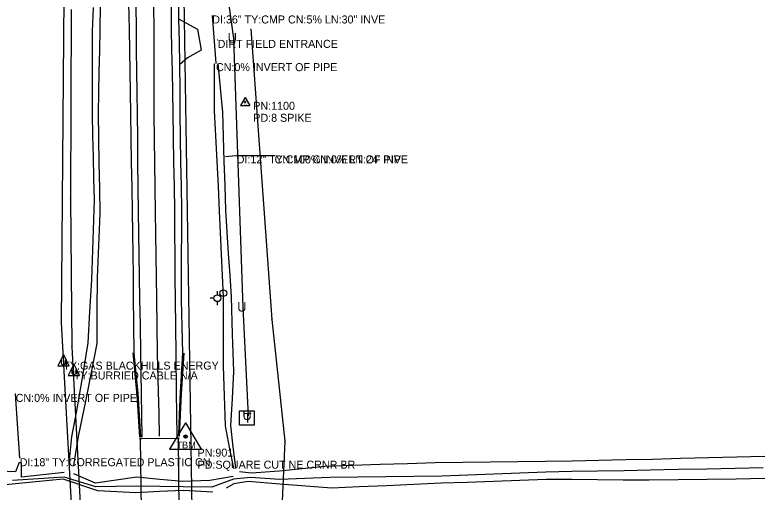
# Model space of a CAD drawing. Extents: x 1804576 to 1805329, y 515859 to 519427.
# Drawn here: x 1804860.5 to 1805328.7, y 517731.6 to 518029.7 of the extents above; entities that cross this region are included whole.
import ezdxf

# ---------------------------------------------------------------- set-up
doc = ezdxf.new("R2010")
doc.units = 0
for name, color, linetype in [('Default', 7, 'Continuous'), ('S_BASELINE', 7, 'Continuous'), ('S_BRIDGE', 7, 'Continuous'), ('S_DITCHLINE', 7, 'Continuous'), ('S_DRG_PT_SYM', 7, 'Continuous'), ('S_EDGE_PAVEMENT', 7, 'Continuous'), ('S_FIBER_OPTIC_CABLE', 7, 'Continuous'), ('S_GAS_UTILITIES', 7, 'Continuous'), ('S_GUARDRAIL', 7, 'Continuous'), ('S_MSC_PT_SYM', 7, 'Continuous'), ('S_PAVEMENT_CROWN', 7, 'Continuous'), ('S_PRIMARY_CTL', 7, 'Continuous'), ('S_PRIMARY_CTL_ANNOT', 7, 'Continuous'), ('S_RDW_PT_SYM', 7, 'Continuous'), ('S_SECONDARY_CTL', 7, 'Continuous'), ('S_SECONDARY_CTL_ANNOT', 7, 'Continuous'), ('S_SHOULDER', 7, 'Continuous'), ('S_SIDE_DRAIN', 7, 'Continuous'), ('S_SIDE_DRAIN_ANNOT', 7, 'Continuous'), ('S_STR_PT_SYM', 7, 'Continuous'), ('S_STREAM', 7, 'Continuous'), ('S_SURVEY_TEXT_ANNOT', 7, 'Continuous'), ('S_TELEPHONE_UTILITIES', 7, 'Continuous'), ('S_UNDERGROUND_CABLE', 7, 'Continuous'), ('S_UTILITY_POLE', 7, 'Continuous'), ('S_UTILITY_POLE_ANNOT', 7, 'Continuous'), ('S_UTL_PT_SYM', 7, 'Continuous'), ('S_WATER_UTILITIES', 7, 'Continuous')]:
    doc.layers.add(name, color=color, linetype=linetype)

msp = doc.modelspace()

# ---------------------------------------------------------------- linework, layer by layer
at = {"layer": 'S_BASELINE'}
msp.add_line((1804971.48, 517701.71), (1804956.7, 518650.01), dxfattribs=at)
at = {"layer": 'S_BRIDGE'}
for p, q in [((1804962.51, 517765.12), (1804938.7, 517764.9)), ((1804938.7, 517764.9), (1804939.34, 517710.14)), ((1804963.12, 517709.92), (1804962.51, 517765.12))]:
    msp.add_line(p, q, dxfattribs=at)
at = {"layer": 'S_DITCHLINE'}
for points in [[(1804913.71, 518035.48), (1804913.53, 518020.43), (1804913.24, 518007.38), (1804912.95, 517994.34), (1804912.66, 517981.29), (1804912.36, 517968.24), (1804912.67, 517952.61), (1804912.98, 517936.98), (1804913.28, 517921.36), (1804913.59, 517905.73), (1804912.67, 517885.64), (1804911.75, 517865.55), (1804911.69, 517844.94), (1804911.63, 517824.33), (1804908.12, 517806.31), (1804904.61, 517788.3), (1804899.95, 517766.31), (1804897.02, 517748.26)], [(1804909.37, 518034.43), (1804908.79, 518019.3), (1804908.77, 518006.38), (1804908.74, 517993.46), (1804908.72, 517980.54), (1804908.69, 517967.62), (1804909, 517954.28), (1804909.31, 517940.94), (1804909.62, 517927.61), (1804909.93, 517914.27), (1804909.51, 517901.75), (1804909.09, 517889.24), (1804908.67, 517876.72), (1804908.25, 517864.2), (1804907.14, 517844.47), (1804906.03, 517824.74), (1804902.39, 517803.02), (1804898.75, 517781.29), (1804895.9, 517766.12), (1804894.15, 517749.44)], [(1804985.12, 517999.01), (1804984.78, 517999.09), (1804984.83, 517984.42), (1804984.88, 517969.74), (1804985.68, 517954.08), (1804986.48, 517938.42), (1804987.28, 517922.76), (1804988.09, 517907.1), (1804988.69, 517893.68), (1804989.29, 517880.25), (1804989.9, 517866.83), (1804990.5, 517853.4), (1804990.47, 517831.79), (1804990.43, 517810.18), (1804991.06, 517791.61), (1804991.69, 517773.04), (1804994.27, 517759.64), (1804996.86, 517746.25)], [(1804987.06, 517999.41), (1804988.57, 517984.22), (1804990.08, 517969.02), (1804990.55, 517953.71), (1804991.01, 517938.39), (1804991.48, 517923.07), (1804991.94, 517907.75), (1804992.82, 517894.23), (1804993.7, 517880.7), (1804994.57, 517867.18), (1804995.45, 517853.65), (1804996.19, 517830.26), (1804996.93, 517806.87), (1804996.01, 517790.01), (1804995.1, 517773.14), (1804996.61, 517759.89), (1804998.12, 517746.64)], [(1804991.99, 517941.17), (1804998.45, 517941.88)]]:
    msp.add_lwpolyline(points, dxfattribs=at)
at = {"layer": 'S_DRG_PT_SYM'}
for points in [[(1804983.65, 518029.36), (1804983.65, 518029.41), (1804983.65, 518029.36), (1804983.6, 518029.36), (1804983.65, 518029.36), (1804983.65, 518029.31), (1804983.65, 518029.36), (1804983.7, 518029.36)], [(1804986, 517999.57), (1804986, 517999.62), (1804986, 517999.57), (1804985.95, 517999.57), (1804986, 517999.57), (1804986, 517999.52), (1804986, 517999.57), (1804986.05, 517999.57)], [(1804998.95, 517941.96), (1804998.95, 517942.01), (1804998.95, 517941.96), (1804998.9, 517941.96), (1804998.95, 517941.96), (1804998.95, 517941.91), (1804998.95, 517941.96), (1804999, 517941.96)], [(1805022.6, 517941.9), (1805022.6, 517941.95), (1805022.6, 517941.9), (1805022.55, 517941.9), (1805022.6, 517941.9), (1805022.6, 517941.85), (1805022.6, 517941.9), (1805022.65, 517941.9)], [(1804860.96, 517792.93), (1804860.96, 517792.98), (1804860.96, 517792.93), (1804860.91, 517792.93), (1804860.96, 517792.93), (1804860.96, 517792.88), (1804860.96, 517792.93), (1804861.01, 517792.93)], [(1804863.51, 517752.75), (1804863.51, 517752.8), (1804863.51, 517752.75), (1804863.46, 517752.75), (1804863.51, 517752.75), (1804863.51, 517752.7), (1804863.51, 517752.75), (1804863.56, 517752.75)]]:
    msp.add_lwpolyline(points, dxfattribs=at)
at = {"layer": 'S_EDGE_PAVEMENT'}
for points in [[(1804958.01, 518041.11), (1804958.03, 518020.98), (1804958.3, 518007.82), (1804958.57, 517994.65), (1804958.85, 517981.49), (1804959.12, 517968.32), (1804959.34, 517953.08), (1804959.57, 517937.84), (1804959.8, 517922.6), (1804960.03, 517907.36), (1804960.14, 517893.43), (1804960.26, 517879.5), (1804960.37, 517865.58), (1804960.48, 517851.65), (1804960.72, 517834.92), (1804960.96, 517818.19), (1804961.15, 517793.95), (1804961.35, 517780.35), (1804961.55, 517766.75)], [(1804935.89, 518035.71), (1804936.1, 518021), (1804936.27, 518007.71), (1804936.45, 517994.43), (1804936.63, 517981.15), (1804936.8, 517967.87), (1804936.96, 517952.61), (1804937.11, 517937.35), (1804937.27, 517922.09), (1804937.42, 517906.83), (1804937.65, 517893.23), (1804937.87, 517879.62), (1804938.1, 517866.02), (1804938.32, 517852.42), (1804938.58, 517835.57), (1804938.83, 517818.71), (1804939.04, 517805.94), (1804939.25, 517793.16), (1804939.43, 517779.49), (1804939.62, 517765.81)], [(1804962.68, 518027.24), (1804974.55, 518020.85), (1804976.66, 518007.75), (1804968.17, 518002.88), (1804963.33, 517998.5)]]:
    msp.add_lwpolyline(points, dxfattribs=at)
at = {"layer": 'S_FIBER_OPTIC_CABLE'}
for p, q in [((1804895.65, 518033.06), (1804895.12, 517915.08)), ((1804895.12, 517915.08), (1804895.93, 517822.38)), ((1804895.93, 517822.38), (1804902.15, 517708.69))]:
    msp.add_line(p, q, dxfattribs=at)
at = {"layer": 'S_GAS_UTILITIES'}
for p, q in [((1804891.14, 518041.91), (1804889.37, 517837.53)), ((1804889.37, 517837.53), (1804897.25, 517695.47))]:
    msp.add_line(p, q, dxfattribs=at)
at = {"layer": 'S_GUARDRAIL'}
for p, q in [((1804934.14, 517818.53), (1804936.62, 517792.02)), ((1804965.9, 517818.28), (1804964.18, 517792.93)), ((1804936.62, 517792.02), (1804938.31, 517766.07)), ((1804964.18, 517792.93), (1804963.03, 517766.47))]:
    msp.add_line(p, q, dxfattribs=at)
at = {"layer": 'S_MSC_PT_SYM'}
msp.add_lwpolyline([(1804987.06, 518014.13), (1804987.06, 518014.18), (1804987.06, 518014.13), (1804987.01, 518014.13), (1804987.06, 518014.13), (1804987.06, 518014.08), (1804987.06, 518014.13), (1804987.11, 518014.13)], dxfattribs=at)
at = {"layer": 'S_PAVEMENT_CROWN'}
msp.add_lwpolyline([(1804947.1, 518035.51), (1804947.26, 518020.62), (1804947.26, 518007.32), (1804947.27, 517994.03), (1804947.27, 517980.73), (1804947.28, 517967.43), (1804947.45, 517952.23), (1804947.61, 517937.03), (1804947.78, 517921.84), (1804947.95, 517906.64), (1804948.18, 517893.02), (1804948.41, 517879.41), (1804948.64, 517865.79), (1804948.87, 517852.18), (1804949.09, 517835.31), (1804949.31, 517818.44), (1804949.91, 517794.33), (1804950.25, 517780.37), (1804950.59, 517766.42)], dxfattribs=at)
at = {"layer": 'S_PRIMARY_CTL'}
for p, q in [((1804966.99, 517774.9), (1804956.96, 517758.39)), ((1804966.99, 517774.9), (1804976.81, 517758.39)), ((1804956.96, 517758.39), (1804976.81, 517758.39))]:
    msp.add_line(p, q, dxfattribs=at)
for radius in [1.04, 0.609, 0.344]:
    msp.add_circle((1804966.99, 517766.2), radius, dxfattribs=at)
at = {"layer": 'S_RDW_PT_SYM'}
for points in [[(1804934.14, 517818.53), (1804934.14, 517818.58), (1804934.14, 517818.53), (1804934.09, 517818.53), (1804934.14, 517818.53), (1804934.14, 517818.48), (1804934.14, 517818.53), (1804934.19, 517818.53)], [(1804965.9, 517818.28), (1804965.9, 517818.33), (1804965.9, 517818.28), (1804965.85, 517818.28), (1804965.9, 517818.28), (1804965.9, 517818.23), (1804965.9, 517818.28), (1804965.95, 517818.28)], [(1804936.62, 517792.02), (1804936.62, 517792.07), (1804936.62, 517792.02), (1804936.57, 517792.02), (1804936.62, 517792.02), (1804936.62, 517791.97), (1804936.62, 517792.02), (1804936.67, 517792.02)], [(1804964.18, 517792.93), (1804964.18, 517792.98), (1804964.18, 517792.93), (1804964.13, 517792.93), (1804964.18, 517792.93), (1804964.18, 517792.88), (1804964.18, 517792.93), (1804964.23, 517792.93)], [(1804938.31, 517766.07), (1804938.31, 517766.12), (1804938.31, 517766.07), (1804938.26, 517766.07), (1804938.31, 517766.07), (1804938.31, 517766.02), (1804938.31, 517766.07), (1804938.36, 517766.07)], [(1804963.03, 517766.47), (1804963.03, 517766.52), (1804963.03, 517766.47), (1804962.98, 517766.47), (1804963.03, 517766.47), (1804963.03, 517766.42), (1804963.03, 517766.47), (1804963.08, 517766.47)]]:
    msp.add_lwpolyline(points, dxfattribs=at)
at = {"layer": 'S_SECONDARY_CTL'}
for p, q in [((1805004.29, 517978.04), (1805001.28, 517973.09)), ((1805004.29, 517978.04), (1805007.24, 517973.09)), ((1805001.28, 517973.09), (1805007.24, 517973.09))]:
    msp.add_line(p, q, dxfattribs=at)
for radius in [0.311, 0.183, 0.103]:
    msp.add_circle((1805004.29, 517975.43), radius, dxfattribs=at)
at = {"layer": 'S_SHOULDER'}
for points in [[(1804931.49, 518037.31), (1804931.74, 518020.57), (1804931.95, 518007.44), (1804932.16, 517994.32), (1804932.37, 517981.19), (1804932.58, 517968.06), (1804932.86, 517952.73), (1804933.15, 517937.4), (1804933.43, 517922.07), (1804933.72, 517906.74), (1804933.88, 517893.48), (1804934.04, 517880.21), (1804934.21, 517866.95), (1804934.37, 517853.68), (1804934.51, 517836.07), (1804934.64, 517818.46), (1804935.89, 517805.92), (1804937.13, 517793.37), (1804937.98, 517779.58), (1804938.84, 517765.78)], [(1804962.51, 518040.03), (1804962.67, 518027.32), (1804963, 518012.92), (1804963.33, 517998.52), (1804963.34, 517983.44), (1804963.36, 517968.36), (1804963.64, 517953.17), (1804963.92, 517937.98), (1804964.2, 517922.8), (1804964.49, 517907.61), (1804964.42, 517893.61), (1804964.35, 517879.61), (1804964.29, 517865.62), (1804964.22, 517851.62), (1804964.62, 517835.06), (1804965.03, 517818.5), (1804963.56, 517793.85), (1804963.07, 517780.26), (1804962.58, 517766.68)]]:
    msp.add_lwpolyline(points, dxfattribs=at)
at = {"layer": 'S_SIDE_DRAIN'}
for p, q in [((1804983.65, 518029.36), (1804986, 517999.57)), ((1804998.95, 517941.96), (1805022.6, 517941.9)), ((1804863.51, 517752.75), (1804860.96, 517792.93))]:
    msp.add_line(p, q, dxfattribs=at)
at = {"layer": 'S_STR_PT_SYM'}
for points in [[(1804938.7, 517764.9), (1804938.7, 517765.4), (1804938.7, 517764.9), (1804938.2, 517764.9), (1804938.7, 517764.9), (1804938.7, 517764.4), (1804938.7, 517764.9), (1804939.2, 517764.9)], [(1804962.51, 517765.12), (1804962.51, 517765.62), (1804962.51, 517765.12), (1804962.01, 517765.12), (1804962.51, 517765.12), (1804962.51, 517764.62), (1804962.51, 517765.12), (1804963.01, 517765.12)]]:
    msp.add_lwpolyline(points, dxfattribs=at)
at = {"layer": 'S_STREAM'}
for points in [[(1804891.18, 517743.82), (1804877.94, 517742.32), (1804864.7, 517740.81), (1804864.65, 517749.6), (1804863.08, 517749.98), (1804860.8, 517744.12), (1804845.91, 517744.83), (1804831.02, 517745.55), (1804815.66, 517744.74), (1804800.29, 517743.92), (1804784.93, 517743.11), (1804769.56, 517742.3), (1804753.95, 517742.37), (1804738.34, 517742.44), (1804722.73, 517742.52), (1804707.12, 517742.59), (1804689.69, 517741.98), (1804672.25, 517741.37), (1804654.82, 517740.76), (1804637.38, 517740.15), (1804623.03, 517739.12), (1804608.68, 517738.09), (1804594.32, 517737.06), (1804579.97, 517736.03)], [(1805328.55, 517753.75), (1805311.05, 517753.32), (1805293.56, 517752.88), (1805276.06, 517752.45), (1805258.57, 517752.01), (1805241.8, 517751.67), (1805225.03, 517751.33), (1805208.26, 517750.99), (1805191.49, 517750.65), (1805174.33, 517750.45), (1805157.17, 517750.26), (1805140.01, 517750.07), (1805122.86, 517749.87), (1805105.65, 517749.3), (1805088.45, 517748.72), (1805071.25, 517748.15), (1805054.04, 517747.58), (1805039.73, 517746.06), (1805025.41, 517744.54), (1805008.18, 517743.49), (1805000.64, 517744.21)], [(1805327.64, 517746.68), (1805310, 517746.33), (1805292.35, 517745.97), (1805274.71, 517745.61), (1805257.07, 517745.26), (1805240.76, 517744.95), (1805224.45, 517744.65), (1805208.14, 517744.34), (1805191.83, 517744.04), (1805175.63, 517743.4), (1805159.43, 517742.75), (1805143.22, 517742.11), (1805127.02, 517741.47), (1805109.55, 517741.25), (1805092.08, 517741.02), (1805074.61, 517740.8), (1805057.14, 517740.58), (1805041.52, 517740.04), (1805025.9, 517739.49), (1805007.57, 517740.75), (1804996.91, 517739.6), (1804983.46, 517734.68), (1804965.49, 517734.77), (1804950.86, 517735.01), (1804936.23, 517735.25), (1804923.59, 517735.09), (1804910.95, 517734.94), (1804891.24, 517740.95), (1804875.1, 517739.9), (1804858.96, 517738.85)], [(1804996.76, 517741.41), (1804982.23, 517738.81), (1804965.31, 517738.16), (1804950.98, 517739.53), (1804936.65, 517740.89), (1804923.75, 517738.97), (1804910.86, 517737.04), (1804897.18, 517742.99)], [(1804984.11, 517731.52), (1804965.43, 517732.59), (1804950.73, 517731.88), (1804936.03, 517731.18), (1804912.17, 517732.34), (1804890.54, 517739.69), (1804873.63, 517738.04), (1804856.73, 517736.4), (1804840.8, 517735.72), (1804824.87, 517735.03), (1804810.22, 517734.71), (1804795.57, 517734.39), (1804780.92, 517734.07), (1804766.27, 517733.74), (1804749.82, 517734.36), (1804733.38, 517734.97), (1804716.93, 517735.58), (1804700.49, 517736.2), (1804684.14, 517734.26), (1804667.78, 517732.33), (1804651.43, 517730.4)], [(1805328.72, 517739.97), (1805310.62, 517739.72), (1805292.52, 517739.47), (1805274.42, 517739.22), (1805256.31, 517738.97), (1805240.25, 517739.1), (1805224.18, 517739.24), (1805208.11, 517739.38), (1805192.04, 517739.51), (1805175.68, 517738.9), (1805159.33, 517738.28), (1805142.98, 517737.66), (1805126.62, 517737.04), (1805109.52, 517736.28), (1805092.42, 517735.51), (1805075.32, 517734.75), (1805058.22, 517733.99), (1805042.08, 517735.2), (1805025.95, 517736.42), (1805006.18, 517738.21), (1804997.25, 517736.7), (1804992.36, 517733.97)]]:
    msp.add_lwpolyline(points, dxfattribs=at)
at = {"layer": 'S_TELEPHONE_UTILITIES'}
msp.add_lwpolyline([(1805000.77, 517773.43), (1805000.77, 517782.43), (1805009.77, 517782.43), (1805009.77, 517773.43)], close=True, dxfattribs=at)
at = {"layer": 'S_UNDERGROUND_CABLE'}
for p, q in [((1804989.64, 518067.35), (1804996.91, 518014.92)), ((1804996.91, 518014.92), (1805002.87, 517846.92)), ((1805002.87, 517846.92), (1805006.18, 517779.17)), ((1804890.74, 517817.62), (1804887.21, 517810.53)), ((1804890.74, 517817.62), (1804894.23, 517810.53)), ((1804889.54, 517811.77), (1804889.54, 517814.21)), ((1804890.16, 517811.11), (1804889.54, 517811.77)), ((1804891.36, 517811.11), (1804890.16, 517811.11)), ((1804891.9, 517811.77), (1804891.36, 517811.11)), ((1804891.9, 517814.21), (1804891.9, 517811.77)), ((1804897.34, 517811.47), (1804893.81, 517804.38)), ((1804897.34, 517811.47), (1804900.83, 517804.38)), ((1804887.21, 517810.53), (1804894.23, 517810.53)), ((1804896.14, 517805.62), (1804896.14, 517808.06)), ((1804898.5, 517808.06), (1804898.5, 517805.62)), ((1804893.81, 517804.38), (1804900.83, 517804.38)), ((1804896.76, 517804.96), (1804896.14, 517805.62)), ((1804897.96, 517804.96), (1804896.76, 517804.96)), ((1804898.5, 517805.62), (1804897.96, 517804.96))]:
    msp.add_line(p, q, dxfattribs=at)
at = {"layer": 'S_UTILITY_POLE'}
for p, q in [((1804990.57, 517857.96), (1804990.57, 517860.09)), ((1804986.86, 517854.81), (1804986.86, 517857.06)), ((1804990.57, 517853.74), (1804990.57, 517851.69)), ((1804984.77, 517852.68), (1804982.45, 517852.68)), ((1804986.94, 517848.27), (1804986.94, 517850.59))]:
    msp.add_line(p, q, dxfattribs=at)
for centre, radius in [((1804990.6, 517855.88), 2.11), ((1804986.87, 517852.7), 2.13)]:
    msp.add_circle(centre, radius, dxfattribs=at)
at = {"layer": 'S_UTL_PT_SYM'}
for points in [[(1805007.8, 518021.05), (1805007.8, 518021.1), (1805007.8, 518021.05), (1805007.75, 518021.05), (1805007.8, 518021.05), (1805007.8, 518021), (1805007.8, 518021.05), (1805007.85, 518021.05)], [(1804895.12, 517915.08), (1804895.12, 517915.13), (1804895.12, 517915.08), (1804895.07, 517915.08), (1804895.12, 517915.08), (1804895.12, 517915.03), (1804895.12, 517915.08), (1804895.17, 517915.08)], [(1805020.86, 517839.48), (1805020.86, 517839.53), (1805020.86, 517839.48), (1805020.81, 517839.48), (1805020.86, 517839.48), (1805020.86, 517839.43), (1805020.86, 517839.48), (1805020.91, 517839.48)], [(1804889.37, 517837.53), (1804889.37, 517837.58), (1804889.37, 517837.53), (1804889.32, 517837.53), (1804889.37, 517837.53), (1804889.37, 517837.48), (1804889.37, 517837.53), (1804889.42, 517837.53)], [(1804895.93, 517822.38), (1804895.93, 517822.43), (1804895.93, 517822.38), (1804895.88, 517822.38), (1804895.93, 517822.38), (1804895.93, 517822.33), (1804895.93, 517822.38), (1804895.98, 517822.38)], [(1805029.04, 517763.32), (1805029.04, 517763.37), (1805029.04, 517763.32), (1805028.99, 517763.32), (1805029.04, 517763.32), (1805029.04, 517763.27), (1805029.04, 517763.32), (1805029.09, 517763.32)]]:
    msp.add_lwpolyline(points, dxfattribs=at)
at = {"layer": 'S_WATER_UTILITIES'}
for p, q in [((1805007.8, 518021.05), (1805020.86, 517839.48)), ((1805020.86, 517839.48), (1805029.04, 517763.32)), ((1805029.04, 517763.32), (1805027.1, 517721.24))]:
    msp.add_line(p, q, dxfattribs=at)

# ---------------------------------------------------------------- texts
at = {"layer": 'Default'}
for p in [(1804993.28, 518012.37), (1804999.24, 517844.38), (1805002.55, 517776.62)]:
    msp.add_text('U', height=6, dxfattribs=at).set_placement(p)
at = {"layer": 'S_PRIMARY_CTL'}
msp.add_text('TBM', height=4.287, dxfattribs=at).set_placement((1804961.34, 517758.81))
at = {"layer": 'S_PRIMARY_CTL_ANNOT'}
for s, p in [('PN:901', (1804974.49, 517753.7)), ('PD:SQUARE CUT NE CRNR BR', (1804974.49, 517746.2))]:
    msp.add_text(s, height=5, dxfattribs=at).set_placement(p)
at = {"layer": 'S_SECONDARY_CTL'}
msp.add_text('TV', height=1.5, dxfattribs=at).set_placement((1805003.08, 517973.42))
at = {"layer": 'S_SECONDARY_CTL_ANNOT'}
for s, p in [('PN:1100', (1805009.29, 517970.43)), ('PD:8 SPIKE', (1805009.29, 517962.93))]:
    msp.add_text(s, height=5, dxfattribs=at).set_placement(p)
at = {"layer": 'S_SIDE_DRAIN_ANNOT'}
for s, p in [('DI:36" TY:CMP CN:5% LN:30" INVE', (1804983.65, 518024.36)), ('CN:0% INVERT OF PIPE', (1804986, 517994.57)), ('DI:12" TY:CMP CN:0% LN:24\' INVE', (1804998.95, 517936.96)), ('CN:100% INVERT OF PIPE', (1805022.6, 517936.9)), ('CN:0% INVERT OF PIPE', (1804860.96, 517787.93)), ('DI:18" TY:CORREGATED PLASTIC CN', (1804863.51, 517747.75))]:
    msp.add_text(s, height=5, dxfattribs=at).set_placement(p)
at = {"layer": 'S_SURVEY_TEXT_ANNOT'}
msp.add_text('DIRT FIELD ENTRANCE', height=5, dxfattribs=at).set_placement((1804987.06, 518009.13))
at = {"layer": 'S_TELEPHONE_UTILITIES'}
msp.add_text('T', height=6, dxfattribs=at).set_placement((1805003.33, 517774.93))
at = {"layer": 'S_UTILITY_POLE_ANNOT'}
for s, p in [('TY:GAS BLACKHILLS ENERGY', (1804890.74, 517808.09)), ('TY:BURRIED CABLE N/A', (1804897.34, 517801.94))]:
    msp.add_text(s, height=5, dxfattribs=at).set_placement(p)

doc.saveas('drawing.dxf')
